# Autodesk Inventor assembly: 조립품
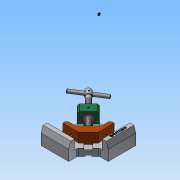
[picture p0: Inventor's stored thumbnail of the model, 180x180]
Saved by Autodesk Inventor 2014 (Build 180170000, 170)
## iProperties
Created: 2020-05
Part Number: 조립품
Document SubType Name: Assembly
Designer: net
Author: net
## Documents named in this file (11)
- C:\Users\net\Desktop\700506V1044\조립품.iam
- C:\Users\net\Desktop\700506V1044\리드스크류.ipt
- C:\Users\net\Desktop\700506V1044\멈춤나사 M4x5.ipt
- C:\Users\net\Desktop\700506V1044\멈춤나사 M4x10.ipt
- C:\Users\net\Desktop\700506V1044\본체.ipt
- C:\Users\net\Desktop\700506V1044\볼트 M4x16.ipt
- C:\Users\net\Desktop\700506V1044\부시.ipt
- C:\Users\net\Desktop\700506V1044\서포트.ipt
- C:\Users\net\Desktop\700506V1044\조.ipt
- C:\Users\net\Desktop\700506V1044\평행 핀 2.5x24.ipt
- C:\Users\net\Desktop\700506V1044\핸들.ipt
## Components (1 placed, 1 different names)
1. 핸들:1
